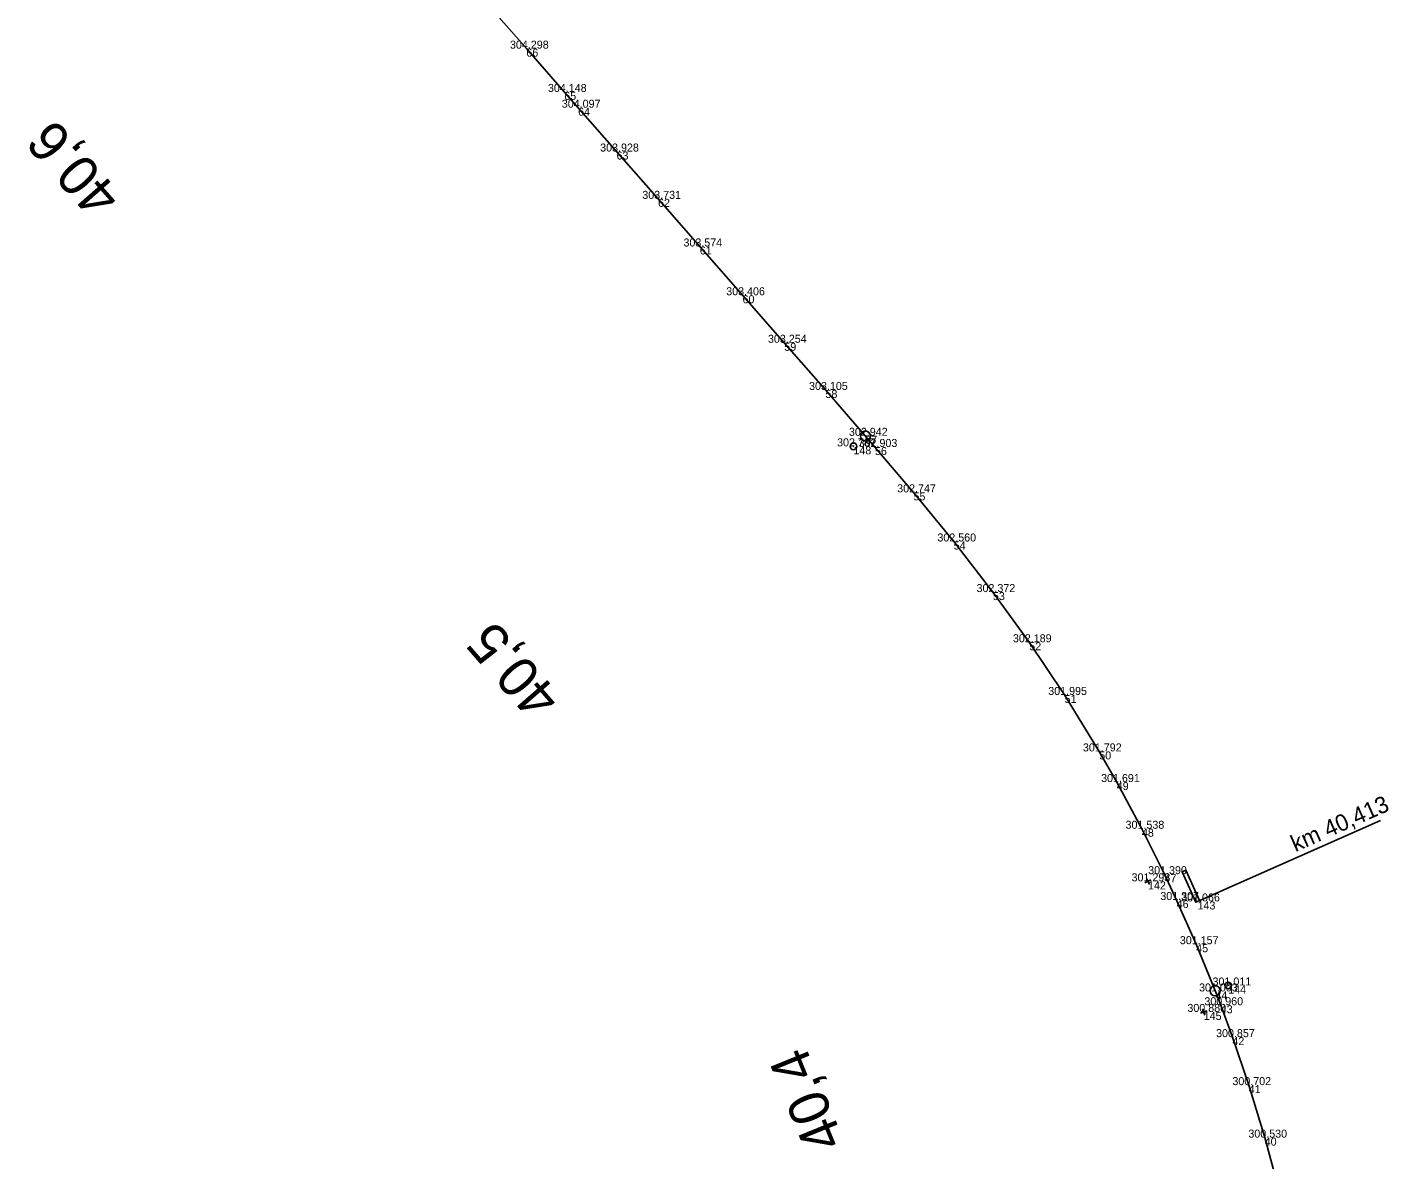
# Model space of a CAD drawing. Extents: x -684938 to -684389, y -1007777 to -1006471.
# Drawn here: x -684671.2 to -684467, y -1006966.7 to -1006797 of the extents above; entities that cross this region are included whole.
import ezdxf

# ---------------------------------------------------------------- set-up
doc = ezdxf.new("R2010")
doc.units = 0
for name, color, linetype in [('Vrstva 1', 7, 'Continuous'), ('Vrstva 60', 7, 'Continuous'), ('Vrstva 61', 7, 'Continuous'), ('Vrstva 7', 7, 'Continuous'), ('Vrstva 9', 7, 'Continuous')]:
    doc.layers.add(name, color=color, linetype=linetype)

msp = doc.modelspace()

# ---------------------------------------------------------------- linework, layer by layer
at = {"layer": 'Vrstva 1'}
msp.add_lwpolyline([(-684483.69, -1006970.61), (-684485.64, -1006963.4), (-684488.03, -1006955.53), (-684490.48, -1006948.34), (-684492.23, -1006943.56), (-684493.03, -1006941.49), (-684495.91, -1006934.41), (-684498.84, -1006927.79), (-684500.66, -1006923.92), (-684504.05, -1006917.11), (-684507.82, -1006910.11), (-684510.44, -1006905.52), (-684515.64, -1006897.06), (-684520.93, -1006889.16), (-684526.39, -1006881.64), (-684532.26, -1006874.06), (-684538.29, -1006866.7), (-684544.07, -1006859.9), (-684545.52, -1006858.22), (-684551.49, -1006851.35), (-684557.66, -1006844.28), (-684563.92, -1006837.16), (-684570.33, -1006829.85), (-684576.59, -1006822.71), (-684582.81, -1006815.62), (-684588.57, -1006809.05), (-684590.65, -1006806.69), (-684596.33, -1006800.2), (-684601.97, -1006793.78)], dxfattribs=at)
at = {"layer": 'Vrstva 60'}
for p, q in [((-684596.33, -1006800.2), (-684596.33, -1006800.2)), ((-684590.65, -1006806.69), (-684590.65, -1006806.69)), ((-684588.57, -1006809.05), (-684588.57, -1006809.05)), ((-684582.81, -1006815.62), (-684582.81, -1006815.62)), ((-684576.59, -1006822.71), (-684576.59, -1006822.71)), ((-684570.33, -1006829.85), (-684570.33, -1006829.85)), ((-684563.92, -1006837.16), (-684563.92, -1006837.16)), ((-684557.66, -1006844.28), (-684557.66, -1006844.28)), ((-684551.49, -1006851.35), (-684551.49, -1006851.35)), ((-684545.52, -1006858.22), (-684545.52, -1006858.22)), ((-684547.3, -1006859.8), (-684547.3, -1006859.8)), ((-684544.07, -1006859.9), (-684544.07, -1006859.9)), ((-684538.29, -1006866.7), (-684538.29, -1006866.7)), ((-684532.26, -1006874.06), (-684532.26, -1006874.06)), ((-684526.39, -1006881.64), (-684526.39, -1006881.64)), ((-684520.93, -1006889.16), (-684520.93, -1006889.16)), ((-684515.64, -1006897.06), (-684515.64, -1006897.06)), ((-684510.44, -1006905.52), (-684510.44, -1006905.52)), ((-684507.82, -1006910.11), (-684507.82, -1006910.11)), ((-684504.05, -1006917.11), (-684504.05, -1006917.11)), ((-684503.14, -1006924.99), (-684503.14, -1006924.99)), ((-684500.66, -1006923.92), (-684500.66, -1006923.92)), ((-684498.84, -1006927.79), (-684498.84, -1006927.79)), ((-684495.71, -1006928), (-684495.71, -1006928)), ((-684495.91, -1006934.41), (-684495.91, -1006934.41)), ((-684493.03, -1006941.49), (-684493.03, -1006941.49)), ((-684491.11, -1006940.6), (-684491.11, -1006940.6)), ((-684492.23, -1006943.56), (-684492.23, -1006943.56)), ((-684494.78, -1006944.56), (-684494.78, -1006944.56)), ((-684490.48, -1006948.34), (-684490.48, -1006948.34)), ((-684488.03, -1006955.53), (-684488.03, -1006955.53)), ((-684485.64, -1006963.4), (-684485.64, -1006963.4))]:
    msp.add_line(p, q, dxfattribs=at)
at = {"layer": 'Vrstva 7'}
for p, q in [((-684547.26, -1006859.84), (-684547.33, -1006859.76)), ((-684503.59, -1006925.22), (-684502.7, -1006924.77)), ((-684502.92, -1006925.44), (-684503.37, -1006924.55)), ((-684491.09, -1006940.65), (-684491.13, -1006940.56)), ((-684494.61, -1006945.03), (-684494.96, -1006944.09)), ((-684495.25, -1006944.73), (-684494.31, -1006944.39))]:
    msp.add_line(p, q, dxfattribs=at)
for centre, radius in [((-684545.5, -1006858.25), 0.75), ((-684547.3, -1006859.8), 0.5), ((-684493.07, -1006941.4), 0.75), ((-684491.11, -1006940.6), 0.5)]:
    msp.add_circle(centre, radius, dxfattribs=at)
at = {"layer": 'Vrstva 9'}
msp.add_line((-684468.28, -1006915.87), (-684495.71, -1006928), dxfattribs=at)
msp.add_lwpolyline([(-684494.89, -1006927.64), (-684495.44, -1006927.88), (-684495.99, -1006928.12), (-684498.01, -1006923.55), (-684497.46, -1006923.31), (-684495.44, -1006927.88)], dxfattribs=at)

# ---------------------------------------------------------------- texts
at = {"layer": 'Vrstva 60'}
for s, p in [('66', (-684596.33, -1006801.4)), ('65', (-684590.65, -1006807.89)), ('64', (-684588.57, -1006810.25)), ('63', (-684582.81, -1006816.82)), ('62', (-684576.59, -1006823.91)), ('61', (-684570.33, -1006831.05)), ('60', (-684563.92, -1006838.36)), ('59', (-684557.66, -1006845.48)), ('58', (-684551.49, -1006852.55)), ('57', (-684545.52, -1006859.42)), ('148', (-684547.3, -1006861)), ('56', (-684544.07, -1006861.1)), ('55', (-684538.29, -1006867.9)), ('54', (-684532.26, -1006875.26)), ('53', (-684526.39, -1006882.84)), ('52', (-684520.93, -1006890.36)), ('51', (-684515.64, -1006898.26)), ('50', (-684510.44, -1006906.72)), ('49', (-684507.82, -1006911.31)), ('48', (-684504.05, -1006918.31)), ('142', (-684503.14, -1006926.2)), ('47', (-684500.66, -1006925.12)), ('46', (-684498.84, -1006928.99)), ('143', (-684495.71, -1006929.2)), ('45', (-684495.91, -1006935.61)), ('44', (-684493.03, -1006942.69)), ('144', (-684491.11, -1006941.8)), ('43', (-684492.23, -1006944.76)), ('145', (-684494.78, -1006945.76)), ('42', (-684490.48, -1006949.54)), ('41', (-684488.03, -1006956.73)), ('40', (-684485.64, -1006964.6))]:
    msp.add_text(s, height=1.2, dxfattribs=at).set_placement(p)
at = {"layer": 'Vrstva 61'}
for s, p in [('304.298', (-684598.79, -1006800.2)), ('304.148', (-684593.1, -1006806.69)), ('304.097', (-684591.02, -1006809.05)), ('303.928', (-684585.27, -1006815.62)), ('303.731', (-684578.95, -1006822.71)), ('303.574', (-684572.78, -1006829.85)), ('303.406', (-684566.37, -1006837.16)), ('303.254', (-684560.11, -1006844.28)), ('303.105', (-684553.95, -1006851.35)), ('302.942', (-684547.97, -1006858.22)), ('302.787', (-684549.75, -1006859.8)), ('302.903', (-684546.52, -1006859.9)), ('302.747', (-684540.74, -1006866.7)), ('302.560', (-684534.71, -1006874.06)), ('302.372', (-684528.84, -1006881.64)), ('302.189', (-684523.39, -1006889.16)), ('301.995', (-684518.09, -1006897.06)), ('301.792', (-684512.89, -1006905.52)), ('301.691', (-684510.17, -1006910.11)), ('301.538', (-684506.5, -1006917.11)), ('301.390', (-684503.11, -1006923.92)), ('301.293', (-684505.6, -1006924.99)), ('301.307', (-684501.29, -1006927.79)), ('301.066', (-684498.16, -1006928)), ('301.157', (-684498.36, -1006934.41)), ('301.011', (-684493.46, -1006940.6)), ('301.003', (-684495.48, -1006941.49)), ('300.880', (-684497.23, -1006944.56)), ('300.960', (-684494.68, -1006943.56)), ('300.857', (-684492.93, -1006948.34)), ('300.702', (-684490.48, -1006955.53)), ('300.530', (-684488.09, -1006963.4))]:
    msp.add_text(s, height=1.2, dxfattribs=at).set_placement(p)
at = {"layer": 'Vrstva 7'}
for s, rotation, p in [('40,6', 131.3181, (-684656.83, -1006822.24)), ('40,5', 131, (-684590.93, -1006897.43)), ('40,4', 112.1422, (-684548.64, -1006964.02))]:
    msp.add_text(s, height=6, rotation=rotation, dxfattribs=at).set_placement(p)
at = {"layer": 'Vrstva 9'}
msp.add_text('km 40,413', height=2.5, rotation=23.8588, dxfattribs=at).set_placement((-684481.04, -1006920.63))

doc.saveas('drawing.dxf')
